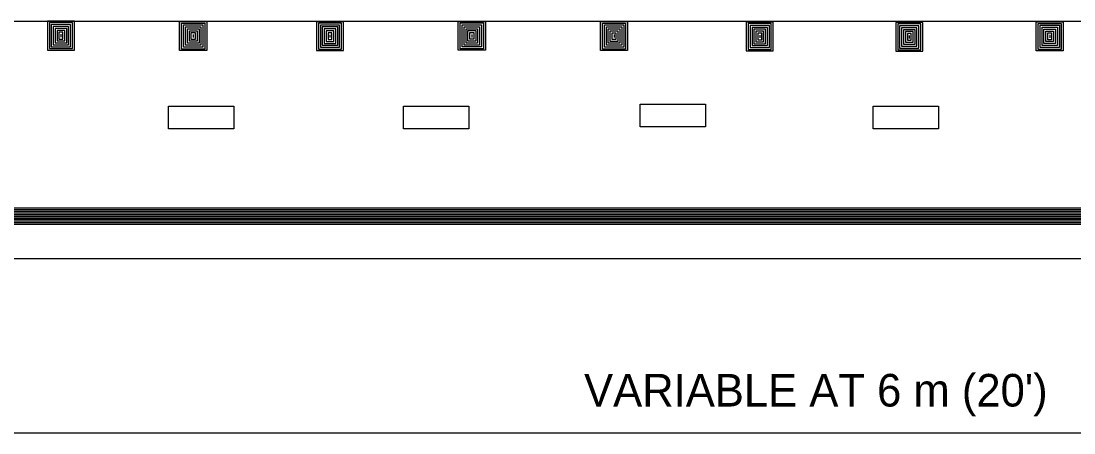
# Model space of a CAD drawing. Extents: x 639362 to 641108, y 298458 to 299646.
# Drawn here: x 639554.2 to 639651.2, y 299464.3 to 299502.2 of the extents above; entities that cross this region are included whole.
import ezdxf

# ---------------------------------------------------------------- set-up
doc = ezdxf.new("R2010")
doc.units = 0
doc.layers.add('2', color=7, linetype='Continuous')

msp = doc.modelspace()

# ---------------------------------------------------------------- linework, layer by layer
at = {"layer": '2'}
for p, q in [((639511.242, 299502.194), (639736.844, 299502.194)), ((639559.164, 299502.18), (639556.668, 299502.18)), ((639556.668, 299502.18), (639556.668, 299499.528)), ((639559.164, 299499.528), (639559.164, 299502.18)), ((639568.845, 299502.146), (639571.342, 299502.146)), ((639568.845, 299499.494), (639568.845, 299502.146)), ((639571.342, 299502.146), (639571.342, 299499.494)), ((639583.937, 299502.136), (639581.441, 299502.136)), ((639581.441, 299502.136), (639581.441, 299499.484)), ((639583.937, 299499.484), (639583.937, 299502.136)), ((639594.495, 299502.154), (639596.991, 299502.154)), ((639594.495, 299499.502), (639594.495, 299502.154)), ((639596.991, 299502.154), (639596.991, 299499.502)), ((639607.589, 299502.142), (639610.086, 299502.142)), ((639607.589, 299499.49), (639607.589, 299502.142)), ((639610.086, 299502.142), (639610.086, 299499.49)), ((639623.503, 299502.104), (639621.007, 299502.104)), ((639621.007, 299502.104), (639621.007, 299499.452)), ((639623.503, 299499.452), (639623.503, 299502.104)), ((639647.698, 299502.114), (639650.196, 299502.114)), ((639647.698, 299499.462), (639647.698, 299502.114)), ((639650.196, 299502.114), (639650.196, 299499.462)), ((639558.98, 299502.047), (639556.851, 299502.047)), ((639556.851, 299502.047), (639556.851, 299499.653)), ((639558.801, 299501.871), (639557.026, 299501.871)), ((639557.026, 299501.871), (639557.026, 299499.831)), ((639558.624, 299501.692), (639557.205, 299501.692)), ((639557.205, 299501.692), (639557.205, 299500.008)), ((639558.448, 299501.515), (639557.383, 299501.515)), ((639557.383, 299501.515), (639557.383, 299500.187)), ((639557.56, 299501.338), (639557.56, 299500.363)), ((639558.269, 299501.338), (639557.56, 299501.338)), ((639558.091, 299501.163), (639557.737, 299501.163)), ((639557.737, 299501.163), (639557.737, 299500.541)), ((639558.091, 299500.541), (639558.091, 299501.163)), ((639558.269, 299500.363), (639558.269, 299501.338)), ((639558.448, 299500.187), (639558.448, 299501.515)), ((639558.624, 299500.008), (639558.624, 299501.692)), ((639558.801, 299499.831), (639558.801, 299501.871)), ((639558.98, 299499.653), (639558.98, 299502.047)), ((639569.03, 299502.014), (639571.159, 299502.014)), ((639569.03, 299499.62), (639569.03, 299502.014)), ((639569.209, 299501.837), (639570.984, 299501.837)), ((639569.209, 299499.798), (639569.209, 299501.837)), ((639569.385, 299501.659), (639570.806, 299501.659)), ((639569.385, 299499.975), (639569.385, 299501.659)), ((639569.565, 299501.482), (639570.629, 299501.482)), ((639569.565, 299500.153), (639569.565, 299501.482)), ((639569.742, 299500.33), (639569.742, 299501.305)), ((639569.742, 299501.305), (639570.449, 299501.305)), ((639569.92, 299501.129), (639570.274, 299501.129)), ((639569.92, 299500.507), (639569.92, 299501.129)), ((639570.274, 299501.129), (639570.274, 299500.507)), ((639570.449, 299501.305), (639570.449, 299500.33)), ((639570.629, 299501.482), (639570.629, 299500.153)), ((639570.806, 299501.659), (639570.806, 299499.975)), ((639570.984, 299501.837), (639570.984, 299499.798)), ((639571.159, 299502.014), (639571.159, 299499.62)), ((639583.752, 299502.004), (639581.623, 299502.004)), ((639581.623, 299502.004), (639581.623, 299499.609)), ((639583.574, 299501.827), (639581.8, 299501.827)), ((639581.8, 299501.827), (639581.8, 299499.788)), ((639583.396, 299501.648), (639581.978, 299501.648)), ((639581.978, 299501.648), (639581.978, 299499.965)), ((639583.22, 299501.471), (639582.155, 299501.471)), ((639582.155, 299501.471), (639582.155, 299500.143)), ((639582.332, 299501.295), (639582.332, 299500.32)), ((639583.042, 299501.295), (639582.332, 299501.295)), ((639582.864, 299501.119), (639582.509, 299501.119)), ((639582.509, 299501.119), (639582.509, 299500.497)), ((639582.864, 299500.497), (639582.864, 299501.119)), ((639583.042, 299500.32), (639583.042, 299501.295)), ((639583.22, 299500.143), (639583.22, 299501.471)), ((639583.396, 299499.965), (639583.396, 299501.648)), ((639583.574, 299499.788), (639583.574, 299501.827)), ((639583.752, 299499.609), (639583.752, 299502.004)), ((639594.68, 299502.022), (639596.809, 299502.022)), ((639594.68, 299499.628), (639594.68, 299502.022)), ((639594.86, 299501.845), (639596.635, 299501.845)), ((639594.86, 299499.806), (639594.86, 299501.845)), ((639595.037, 299501.667), (639596.456, 299501.667)), ((639595.037, 299499.983), (639595.037, 299501.667)), ((639595.212, 299501.49), (639596.277, 299501.49)), ((639595.212, 299500.161), (639595.212, 299501.49)), ((639595.392, 299500.338), (639595.392, 299501.313)), ((639595.392, 299501.313), (639596.101, 299501.313)), ((639595.57, 299501.137), (639595.924, 299501.137)), ((639595.57, 299500.515), (639595.57, 299501.137)), ((639595.924, 299501.137), (639595.924, 299500.515)), ((639596.101, 299501.313), (639596.101, 299500.338)), ((639596.277, 299501.49), (639596.277, 299500.161)), ((639596.456, 299501.667), (639596.456, 299499.983)), ((639596.635, 299501.845), (639596.635, 299499.806)), ((639596.809, 299502.022), (639596.809, 299499.628)), ((639607.774, 299502.009), (639609.903, 299502.009)), ((639607.774, 299499.615), (639607.774, 299502.009)), ((639607.952, 299501.833), (639609.727, 299501.833)), ((639607.952, 299499.793), (639607.952, 299501.833)), ((639608.13, 299501.654), (639609.549, 299501.654)), ((639608.13, 299499.97), (639608.13, 299501.654)), ((639608.307, 299501.477), (639609.372, 299501.477)), ((639608.307, 299500.149), (639608.307, 299501.477)), ((639608.484, 299500.325), (639608.484, 299501.3)), ((639608.484, 299501.3), (639609.195, 299501.3)), ((639608.662, 299501.125), (639609.017, 299501.125)), ((639608.662, 299500.503), (639608.662, 299501.125)), ((639609.017, 299501.125), (639609.017, 299500.503)), ((639609.195, 299501.3), (639609.195, 299500.325)), ((639609.372, 299501.477), (639609.372, 299500.149)), ((639609.549, 299501.654), (639609.549, 299499.97)), ((639609.727, 299501.833), (639609.727, 299499.793)), ((639609.903, 299502.009), (639609.903, 299499.615)), ((639623.318, 299501.971), (639621.189, 299501.971)), ((639621.189, 299501.971), (639621.189, 299499.577)), ((639623.139, 299501.795), (639621.366, 299501.795)), ((639621.366, 299501.795), (639621.366, 299499.755)), ((639622.963, 299501.616), (639621.544, 299501.616)), ((639621.544, 299501.616), (639621.544, 299499.932)), ((639622.786, 299501.439), (639621.721, 299501.439)), ((639621.721, 299501.439), (639621.721, 299500.111)), ((639621.898, 299501.262), (639621.898, 299500.288)), ((639622.609, 299501.262), (639621.898, 299501.262)), ((639622.609, 299500.288), (639622.609, 299501.262)), ((639622.786, 299500.111), (639622.786, 299501.439)), ((639622.963, 299499.932), (639622.963, 299501.616)), ((639623.139, 299499.755), (639623.139, 299501.795)), ((639623.318, 299499.577), (639623.318, 299501.971)), ((639637.27, 299502.061), (639634.773, 299502.061)), ((639634.773, 299502.061), (639634.773, 299499.409)), ((639637.085, 299501.929), (639634.956, 299501.929)), ((639634.956, 299501.929), (639634.956, 299499.535)), ((639636.907, 299501.752), (639635.131, 299501.752)), ((639635.131, 299501.752), (639635.131, 299499.713)), ((639636.727, 299501.574), (639635.31, 299501.574)), ((639635.31, 299501.574), (639635.31, 299499.89)), ((639636.552, 299501.397), (639635.487, 299501.397)), ((639635.487, 299501.397), (639635.487, 299500.068)), ((639635.663, 299501.22), (639635.663, 299500.245)), ((639636.375, 299501.22), (639635.663, 299501.22)), ((639636.375, 299500.245), (639636.375, 299501.22)), ((639636.552, 299500.068), (639636.552, 299501.397)), ((639636.727, 299499.89), (639636.727, 299501.574)), ((639636.907, 299499.713), (639636.907, 299501.752)), ((639637.085, 299499.535), (639637.085, 299501.929)), ((639637.27, 299499.409), (639637.27, 299502.061)), ((639647.884, 299501.982), (639650.013, 299501.982)), ((639647.884, 299499.587), (639647.884, 299501.982)), ((639648.062, 299501.805), (639649.837, 299501.805)), ((639648.062, 299499.766), (639648.062, 299501.805)), ((639648.241, 299501.627), (639649.659, 299501.627)), ((639648.241, 299499.943), (639648.241, 299501.627)), ((639648.418, 299501.45), (639649.482, 299501.45)), ((639648.418, 299500.121), (639648.418, 299501.45)), ((639648.595, 299500.298), (639648.595, 299501.273)), ((639648.595, 299501.273), (639649.305, 299501.273)), ((639648.773, 299501.097), (639649.127, 299501.097)), ((639648.773, 299500.475), (639648.773, 299501.097)), ((639649.127, 299501.097), (639649.127, 299500.475)), ((639649.305, 299501.273), (639649.305, 299500.298)), ((639649.482, 299501.45), (639649.482, 299500.121)), ((639649.659, 299501.627), (639649.659, 299499.943)), ((639649.837, 299501.805), (639649.837, 299499.766)), ((639650.013, 299501.982), (639650.013, 299499.587)), ((639557.383, 299500.187), (639558.448, 299500.187)), ((639557.56, 299500.363), (639558.269, 299500.363)), ((639557.737, 299500.541), (639558.091, 299500.541)), ((639557.915, 299500.983), (639557.915, 299500.718)), ((639570.629, 299500.153), (639569.565, 299500.153)), ((639570.449, 299500.33), (639569.742, 299500.33)), ((639570.274, 299500.507), (639569.92, 299500.507)), ((639570.094, 299500.95), (639570.094, 299500.684)), ((639582.155, 299500.143), (639583.22, 299500.143)), ((639582.332, 299500.32), (639583.042, 299500.32)), ((639582.509, 299500.497), (639582.864, 299500.497)), ((639582.687, 299500.939), (639582.687, 299500.674)), ((639596.277, 299500.161), (639595.212, 299500.161)), ((639596.101, 299500.338), (639595.392, 299500.338)), ((639595.924, 299500.515), (639595.57, 299500.515)), ((639595.745, 299500.958), (639595.745, 299500.692)), ((639609.372, 299500.149), (639608.307, 299500.149)), ((639609.195, 299500.325), (639608.484, 299500.325)), ((639609.017, 299500.503), (639608.662, 299500.503)), ((639608.838, 299500.945), (639608.838, 299500.679)), ((639621.898, 299500.288), (639622.609, 299500.288)), ((639622.431, 299501.087), (639622.074, 299501.087)), ((639622.074, 299501.087), (639622.074, 299500.465)), ((639622.074, 299500.465), (639622.431, 299500.465)), ((639622.254, 299500.907), (639622.254, 299500.642)), ((639622.431, 299500.465), (639622.431, 299501.087)), ((639635.663, 299500.245), (639636.375, 299500.245)), ((639636.195, 299501.044), (639635.842, 299501.044)), ((639635.842, 299501.044), (639635.842, 299500.422)), ((639635.842, 299500.422), (639636.195, 299500.422)), ((639636.021, 299500.865), (639636.021, 299500.599)), ((639636.195, 299500.422), (639636.195, 299501.044)), ((639649.305, 299500.298), (639648.595, 299500.298)), ((639649.127, 299500.475), (639648.773, 299500.475)), ((639648.949, 299500.917), (639648.949, 299500.652)), ((639556.668, 299499.528), (639559.164, 299499.528)), ((639556.851, 299499.653), (639558.98, 299499.653)), ((639557.026, 299499.831), (639558.801, 299499.831)), ((639557.205, 299500.008), (639558.624, 299500.008)), ((639571.342, 299499.494), (639568.845, 299499.494)), ((639571.159, 299499.62), (639569.03, 299499.62)), ((639570.984, 299499.798), (639569.209, 299499.798)), ((639570.806, 299499.975), (639569.385, 299499.975)), ((639581.441, 299499.484), (639583.937, 299499.484)), ((639581.623, 299499.609), (639583.752, 299499.609)), ((639581.8, 299499.788), (639583.574, 299499.788)), ((639581.978, 299499.965), (639583.396, 299499.965)), ((639596.991, 299499.502), (639594.495, 299499.502)), ((639596.809, 299499.628), (639594.68, 299499.628)), ((639596.635, 299499.806), (639594.86, 299499.806)), ((639596.456, 299499.983), (639595.037, 299499.983)), ((639610.086, 299499.49), (639607.589, 299499.49)), ((639609.903, 299499.615), (639607.774, 299499.615)), ((639609.727, 299499.793), (639607.952, 299499.793)), ((639609.549, 299499.97), (639608.13, 299499.97)), ((639621.007, 299499.452), (639623.503, 299499.452)), ((639621.189, 299499.577), (639623.318, 299499.577)), ((639621.366, 299499.755), (639623.139, 299499.755)), ((639621.544, 299499.932), (639622.963, 299499.932)), ((639621.721, 299500.111), (639622.786, 299500.111)), ((639634.773, 299499.409), (639637.27, 299499.409)), ((639634.956, 299499.535), (639637.085, 299499.535)), ((639635.131, 299499.713), (639636.907, 299499.713)), ((639635.31, 299499.89), (639636.727, 299499.89)), ((639635.487, 299500.068), (639636.552, 299500.068)), ((639650.196, 299499.462), (639647.698, 299499.462)), ((639650.013, 299499.587), (639647.884, 299499.587)), ((639649.837, 299499.766), (639648.062, 299499.766)), ((639649.659, 299499.943), (639648.241, 299499.943)), ((639649.482, 299500.121), (639648.418, 299500.121)), ((639567.818, 299492.282), (639567.818, 299494.347)), ((639567.818, 299494.347), (639573.831, 299494.347)), ((639573.831, 299494.347), (639573.831, 299492.282)), ((639589.448, 299492.282), (639589.448, 299494.347)), ((639589.448, 299494.347), (639595.461, 299494.347)), ((639595.461, 299494.347), (639595.461, 299492.282)), ((639611.231, 299492.47), (639611.231, 299494.534)), ((639611.231, 299494.534), (639617.244, 299494.534)), ((639617.244, 299494.534), (639617.244, 299492.47)), ((639632.685, 299492.282), (639632.685, 299494.347)), ((639632.685, 299494.347), (639638.698, 299494.347)), ((639638.698, 299494.347), (639638.698, 299492.282)), ((639617.244, 299492.47), (639611.231, 299492.47)), ((639573.831, 299492.282), (639567.818, 299492.282)), ((639595.461, 299492.282), (639589.448, 299492.282)), ((639638.698, 299492.282), (639632.685, 299492.282)), ((639511.242, 299484.992), (639812.246, 299484.992)), ((639511.242, 299484.842), (639812.246, 299484.842)), ((639511.242, 299484.692), (639812.246, 299484.692)), ((639511.242, 299484.542), (639812.246, 299484.542)), ((639511.242, 299484.392), (639812.246, 299484.392)), ((639511.242, 299484.242), (639812.246, 299484.242)), ((639511.242, 299484.092), (639812.246, 299484.092)), ((639511.242, 299483.942), (639812.246, 299483.942)), ((639511.242, 299483.792), (639812.246, 299483.792)), ((639511.242, 299483.642), (639812.246, 299483.642)), ((639511.242, 299483.492), (639812.246, 299483.492)), ((639511.242, 299480.346), (639812.246, 299480.346)), ((639530.326, 299464.273), (639733.677, 299464.273))]:
    msp.add_line(p, q, dxfattribs=at)

# ---------------------------------------------------------------- texts
msp.add_text("VARIABLE AT 6 m (20')", height=3, dxfattribs=at).set_placement((639606.08, 299466.704))

doc.saveas('drawing.dxf')
